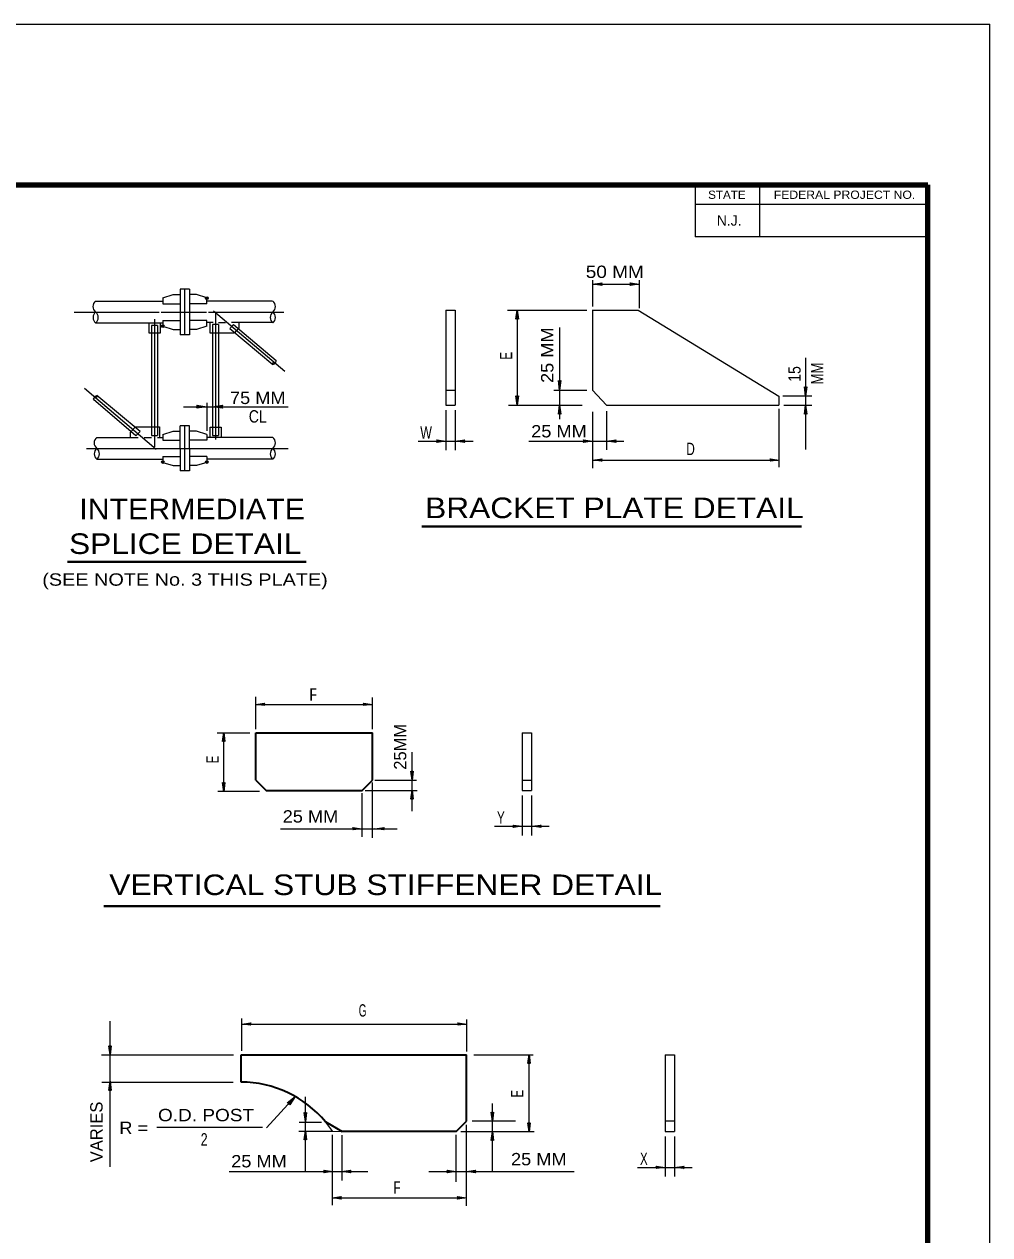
# Model space of a CAD drawing. Extents: x 312601.858 to 312602.699, y 144420.109 to 144420.704.
# Drawn here: x 312602.4645 to 312602.6988, y 144420.4096 to 144420.7035 of the extents above; entities that cross this region are included whole.
import ezdxf
from ezdxf.enums import TextEntityAlignment as Align

# ---------------------------------------------------------------- set-up
doc = ezdxf.new("R2010")
doc.units = 0
doc.header["$LTSCALE"] = 0.0012
doc.header["$PDMODE"] = 32
doc.header["$PDSIZE"] = 0.0006
doc.linetypes.add('DOT_DASHED', pattern=[7.7, 5, -1.2, 0.3, -1.2])
for name, color, linetype, lineweight in [('1', 7, 'Continuous', 13), ('2', 7, 'Continuous', 25), ('39', 7, 'Continuous', 13), ('61', 7, 'Continuous', 25)]:
    doc.layers.add(name, color=color, linetype=linetype, lineweight=lineweight)

msp = doc.modelspace()

# ---------------------------------------------------------------- hatches: boundary and pattern name
at = {"layer": '39'}
for points in [[(312602.5066, 144420.6106), (312602.5064, 144420.611), (312602.5088, 144420.6106), (312602.5064, 144420.6103)], [(312602.5124, 144420.6106), (312602.5126, 144420.6103), (312602.5102, 144420.6106), (312602.5126, 144420.611)], [(312602.5287, 144420.4416), (312602.5283, 144420.4417), (312602.5302, 144420.4432), (312602.5289, 144420.4412)]]:
    msp.add_hatch(color=256, dxfattribs=at).paths.add_polyline_path(points)

# ---------------------------------------------------------------- linework, layer by layer
at = {"layer": '1', "lineweight": 25}
for p, q in [((312602.5023, 144420.6392), (312602.5023, 144420.6281)), ((312602.5046, 144420.6392), (312602.5023, 144420.6392)), ((312602.5034, 144420.6392), (312602.5034, 144420.6281)), ((312602.5046, 144420.6392), (312602.5046, 144420.6281)), ((312602.4818, 144420.6363), (312602.4981, 144420.6363)), ((312602.4981, 144420.6371), (312602.5006, 144420.6379)), ((312602.4981, 144420.6371), (312602.4981, 144420.6356)), ((312602.5006, 144420.6379), (312602.5023, 144420.6379)), ((312602.5063, 144420.6379), (312602.5046, 144420.6379)), ((312602.5088, 144420.6371), (312602.5063, 144420.6379)), ((312602.5088, 144420.6356), (312602.5088, 144420.6371)), ((312602.5247, 144420.6363), (312602.5088, 144420.6363)), ((312602.4981, 144420.6356), (312602.5023, 144420.6356)), ((312602.5088, 144420.6356), (312602.5046, 144420.6356)), ((312602.5668, 144420.6341), (312602.5691, 144420.6341)), ((312602.5668, 144420.6341), (312602.5668, 144420.611)), ((312602.5691, 144420.6341), (312602.5691, 144420.611)), ((312602.6023, 144420.6341), (312602.6135, 144420.6341)), ((312602.6024, 144420.6341), (312602.6024, 144420.6147)), ((312602.6135, 144420.6341), (312602.6476, 144420.6132)), ((312602.4818, 144420.631), (312602.498, 144420.631)), ((312602.4954, 144420.6304), (312602.4954, 144420.6037)), ((312602.4968, 144420.6304), (312602.4954, 144420.6304)), ((312602.4968, 144420.631), (312602.4973, 144420.631)), ((312602.4968, 144420.6304), (312602.4968, 144420.6037)), ((312602.4971, 144420.631), (312602.4973, 144420.631)), ((312602.4973, 144420.631), (312602.4981, 144420.631)), ((312602.4981, 144420.6316), (312602.5023, 144420.6316)), ((312602.4981, 144420.6316), (312602.4981, 144420.6302)), ((312602.4981, 144420.6302), (312602.5006, 144420.6294)), ((312602.5088, 144420.6316), (312602.5046, 144420.6316)), ((312602.5088, 144420.6302), (312602.5063, 144420.6294)), ((312602.5088, 144420.6302), (312602.5088, 144420.6316)), ((312602.5096, 144420.6311), (312602.5088, 144420.6311)), ((312602.5103, 144420.6311), (312602.5096, 144420.6311)), ((312602.5099, 144420.6311), (312602.5096, 144420.6311)), ((312602.5102, 144420.6306), (312602.5102, 144420.6037)), ((312602.5116, 144420.6306), (312602.5102, 144420.6306)), ((312602.5116, 144420.6311), (312602.5133, 144420.6311)), ((312602.5116, 144420.6306), (312602.5116, 144420.6037)), ((312602.5144, 144420.6296), (312602.5153, 144420.6306)), ((312602.5248, 144420.6311), (312602.5148, 144420.6311)), ((312602.5153, 144420.6306), (312602.5256, 144420.6219)), ((312602.5006, 144420.6294), (312602.5023, 144420.6294)), ((312602.5046, 144420.6281), (312602.5023, 144420.6281)), ((312602.5063, 144420.6294), (312602.5046, 144420.6294)), ((312602.5144, 144420.6296), (312602.5248, 144420.6209)), ((312602.4916, 144420.6036), (312602.4813, 144420.6124)), ((312602.4926, 144420.6046), (312602.4821, 144420.6134)), ((312602.5668, 144420.6147), (312602.5691, 144420.6147)), ((312602.6024, 144420.6147), (312602.6058, 144420.611)), ((312602.6476, 144420.6132), (312602.6476, 144420.611)), ((312602.5668, 144420.611), (312602.5691, 144420.611)), ((312602.6058, 144420.611), (312602.6476, 144420.611)), ((312602.4916, 144420.6036), (312602.4926, 144420.6046)), ((312602.4954, 144420.6037), (312602.4968, 144420.6037)), ((312602.4981, 144420.6039), (312602.5006, 144420.6047)), ((312602.4981, 144420.6039), (312602.4981, 144420.6025)), ((312602.5006, 144420.6047), (312602.5023, 144420.6047)), ((312602.5023, 144420.6006), (312602.5023, 144420.606)), ((312602.5034, 144420.606), (312602.5034, 144420.5951)), ((312602.5046, 144420.6006), (312602.5046, 144420.606)), ((312602.5063, 144420.6047), (312602.5046, 144420.6047)), ((312602.5088, 144420.6039), (312602.5063, 144420.6047)), ((312602.5088, 144420.6039), (312602.5088, 144420.6025)), ((312602.5102, 144420.6037), (312602.5116, 144420.6037)), ((312602.4821, 144420.6032), (312602.4921, 144420.6032)), ((312602.4936, 144420.6032), (312602.4954, 144420.6032)), ((312602.4968, 144420.6032), (312602.4973, 144420.6032)), ((312602.4971, 144420.6032), (312602.4973, 144420.6032)), ((312602.4973, 144420.6032), (312602.4981, 144420.6032)), ((312602.4981, 144420.6025), (312602.5023, 144420.6025)), ((312602.5088, 144420.6025), (312602.5046, 144420.6025)), ((312602.5096, 144420.6032), (312602.5088, 144420.6032)), ((312602.5248, 144420.6032), (312602.509, 144420.6032)), ((312602.5102, 144420.6032), (312602.5096, 144420.6032)), ((312602.5099, 144420.6032), (312602.5096, 144420.6032)), ((312602.4821, 144420.5979), (312602.4981, 144420.5979)), ((312602.4981, 144420.5986), (312602.5023, 144420.5986)), ((312602.4981, 144420.5986), (312602.4981, 144420.5971)), ((312602.5023, 144420.6006), (312602.5023, 144420.5951)), ((312602.5046, 144420.6006), (312602.5046, 144420.5951)), ((312602.5088, 144420.5986), (312602.5046, 144420.5986)), ((312602.5088, 144420.5986), (312602.5088, 144420.5971)), ((312602.5248, 144420.5979), (312602.5088, 144420.5979)), ((312602.4981, 144420.5971), (312602.5006, 144420.5964)), ((312602.5006, 144420.5964), (312602.5023, 144420.5964)), ((312602.5063, 144420.5964), (312602.5046, 144420.5964)), ((312602.5088, 144420.5971), (312602.5063, 144420.5964)), ((312602.5853, 144420.5315), (312602.5853, 144420.5175)), ((312602.5853, 144420.5315), (312602.5876, 144420.5315)), ((312602.5876, 144420.5315), (312602.5876, 144420.5175)), ((312602.5853, 144420.52), (312602.5876, 144420.52)), ((312602.5853, 144420.5175), (312602.5876, 144420.5175)), ((312602.62, 144420.4533), (312602.62, 144420.4347)), ((312602.62, 144420.4533), (312602.6223, 144420.4533)), ((312602.6223, 144420.4533), (312602.6223, 144420.4347)), ((312602.62, 144420.4373), (312602.6223, 144420.4373)), ((312602.62, 144420.4347), (312602.6223, 144420.4347))]:
    msp.add_line(p, q, dxfattribs=at)
at = {"layer": '1'}
for p, q in [((312602.6024, 144420.6414), (312602.6024, 144420.635)), ((312602.6024, 144420.6404), (312602.6137, 144420.6404)), ((312602.6137, 144420.6414), (312602.6137, 144420.6346)), ((312602.5818, 144420.6341), (312602.601, 144420.6341)), ((312602.5841, 144420.6341), (312602.5841, 144420.611)), ((312602.6541, 144420.6225), (312602.6541, 144420.6003)), ((312602.593, 144420.6147), (312602.601, 144420.6147)), ((312602.6556, 144420.6132), (312602.6486, 144420.6132)), ((312602.5031, 144420.6106), (312602.5088, 144420.6106)), ((312602.5088, 144420.6116), (312602.5088, 144420.6048)), ((312602.5088, 144420.6106), (312602.5104, 144420.6106)), ((312602.5102, 144420.6106), (312602.5285, 144420.6106)), ((312602.5668, 144420.6098), (312602.5668, 144420.6001)), ((312602.5691, 144420.6098), (312602.5691, 144420.6001)), ((312602.582, 144420.611), (312602.5999, 144420.611)), ((312602.6058, 144420.6096), (312602.6058, 144420.6002)), ((312602.6476, 144420.6101), (312602.6476, 144420.596)), ((312602.6488, 144420.611), (312602.6556, 144420.611)), ((312602.6024, 144420.6094), (312602.6024, 144420.5957)), ((312602.5046, 144420.606), (312602.5023, 144420.606)), ((312602.5601, 144420.6023), (312602.5668, 144420.6023)), ((312602.6024, 144420.5977), (312602.6474, 144420.5977)), ((312602.5046, 144420.5951), (312602.5023, 144420.5951)), ((312602.5207, 144420.5324), (312602.5207, 144420.5402)), ((312602.549, 144420.5324), (312602.549, 144420.5401)), ((312602.5207, 144420.5384), (312602.549, 144420.5384)), ((312602.5113, 144420.5315), (312602.5192, 144420.5315)), ((312602.5129, 144420.5173), (312602.5129, 144420.5316)), ((312602.5586, 144420.5125), (312602.5586, 144420.5268)), ((312602.549, 144420.506), (312602.549, 144420.5194)), ((312602.5496, 144420.52), (312602.5597, 144420.52)), ((312602.5115, 144420.5173), (312602.5216, 144420.5173)), ((312602.5465, 144420.5062), (312602.5465, 144420.5168)), ((312602.5472, 144420.5175), (312602.5598, 144420.5175)), ((312602.5853, 144420.5163), (312602.5853, 144420.5066)), ((312602.5876, 144420.5163), (312602.5876, 144420.5066)), ((312602.5267, 144420.5082), (312602.555, 144420.5082)), ((312602.5786, 144420.5088), (312602.5853, 144420.5088)), ((312602.4853, 144420.4261), (312602.4853, 144420.4615)), ((312602.5173, 144420.4543), (312602.5173, 144420.4621)), ((312602.5173, 144420.4608), (312602.5719, 144420.4608)), ((312602.5719, 144420.4541), (312602.5719, 144420.4619)), ((312602.4832, 144420.4533), (312602.5153, 144420.4533)), ((312602.5736, 144420.4533), (312602.588, 144420.4533)), ((312602.587, 144420.4347), (312602.587, 144420.4533)), ((312602.4833, 144420.4467), (312602.5152, 144420.4467)), ((312602.5302, 144420.4432), (312602.5233, 144420.4356)), ((312602.5327, 144420.425), (312602.5327, 144420.4431)), ((312602.5781, 144420.425), (312602.5781, 144420.4415)), ((312602.5312, 144420.437), (312602.5366, 144420.437)), ((312602.5376, 144420.437), (312602.5393, 144420.4347)), ((312602.5718, 144420.4167), (312602.5718, 144420.4363)), ((312602.5732, 144420.4373), (312602.5837, 144420.4373)), ((312602.5223, 144420.4357), (312602.4967, 144420.4357)), ((312602.5393, 144420.4168), (312602.5393, 144420.4339)), ((312602.5416, 144420.4228), (312602.5416, 144420.4338)), ((312602.5693, 144420.4225), (312602.5693, 144420.4339)), ((312602.5704, 144420.4347), (312602.5882, 144420.4347)), ((312602.62, 144420.4335), (312602.62, 144420.4238)), ((312602.6223, 144420.4335), (312602.6223, 144420.4238)), ((312602.5142, 144420.425), (312602.5479, 144420.425)), ((312602.5627, 144420.425), (312602.5652, 144420.425)), ((312602.5637, 144420.425), (312602.5979, 144420.425)), ((312602.6133, 144420.426), (312602.62, 144420.426)), ((312602.5394, 144420.4186), (312602.5714, 144420.4186))]:
    msp.add_line(p, q, dxfattribs=at)
at = {"layer": '1', "linetype": 'DOT_DASHED'}
for p, q in [((312602.4766, 144420.6336), (312602.4972, 144420.6336)), ((312602.4977, 144420.6336), (312602.5087, 144420.6336)), ((312602.5092, 144420.6336), (312602.5275, 144420.6336)), ((312602.5104, 144420.6339), (312602.5277, 144420.6193)), ((312602.5109, 144420.6333), (312602.5109, 144420.6027)), ((312602.4961, 144420.6319), (312602.4961, 144420.6009)), ((312602.4965, 144420.6003), (312602.4791, 144420.6151)), ((312602.4796, 144420.6005), (312602.5285, 144420.6005))]:
    msp.add_line(p, q, dxfattribs=at)
at = {"layer": '1', "lineweight": 40}
for p, q in [((312602.561, 144420.5816), (312602.6531, 144420.5816)), ((312602.475, 144420.573), (312602.5329, 144420.573)), ((312602.4838, 144420.4894), (312602.6188, 144420.4894))]:
    msp.add_line(p, q, dxfattribs=at)
at = {"layer": '1', "lineweight": 35}
for p, q in [((312602.5207, 144420.52), (312602.5207, 144420.5315)), ((312602.5207, 144420.5315), (312602.549, 144420.5315)), ((312602.549, 144420.52), (312602.549, 144420.5315)), ((312602.5207, 144420.52), (312602.5232, 144420.5175)), ((312602.5465, 144420.5175), (312602.549, 144420.52)), ((312602.5232, 144420.5175), (312602.5465, 144420.5175)), ((312602.5171, 144420.4533), (312602.5718, 144420.4533)), ((312602.5171, 144420.4467), (312602.5171, 144420.4533)), ((312602.5718, 144420.4372), (312602.5718, 144420.4533)), ((312602.5375, 144420.4371), (312602.5416, 144420.4347)), ((312602.5693, 144420.4347), (312602.5718, 144420.4372)), ((312602.5693, 144420.4347), (312602.5416, 144420.4347))]:
    msp.add_line(p, q, dxfattribs=at)
at = {"layer": '1'}
for points in [[(312602.6047, 144420.6401), (312602.6024, 144420.6404), (312602.6047, 144420.6407), (312602.6044, 144420.6404)], [(312602.6115, 144420.6407), (312602.6137, 144420.6404), (312602.6115, 144420.6401), (312602.6117, 144420.6404)], [(312602.5838, 144420.6319), (312602.5841, 144420.6341), (312602.5844, 144420.6319), (312602.5841, 144420.6321)], [(312602.5947, 144420.617), (312602.5944, 144420.6147), (312602.5941, 144420.617), (312602.5944, 144420.6167)], [(312602.6544, 144420.6155), (312602.6541, 144420.6132), (312602.6538, 144420.6155), (312602.6541, 144420.6152)], [(312602.5844, 144420.6133), (312602.5841, 144420.611), (312602.5838, 144420.6133), (312602.5841, 144420.613)], [(312602.5941, 144420.6088), (312602.5944, 144420.611), (312602.5947, 144420.6088), (312602.5944, 144420.609)], [(312602.6538, 144420.6088), (312602.6541, 144420.611), (312602.6544, 144420.6088), (312602.6541, 144420.609)], [(312602.5646, 144420.6026), (312602.5668, 144420.6023), (312602.5646, 144420.602), (312602.5648, 144420.6023)], [(312602.5714, 144420.602), (312602.5691, 144420.6023), (312602.5714, 144420.6026), (312602.5711, 144420.6023)], [(312602.6002, 144420.6026), (312602.6024, 144420.6023), (312602.6002, 144420.602), (312602.6004, 144420.6023)], [(312602.6081, 144420.602), (312602.6058, 144420.6023), (312602.6081, 144420.6026), (312602.6078, 144420.6023)], [(312602.6047, 144420.5974), (312602.6024, 144420.5977), (312602.6047, 144420.598), (312602.6044, 144420.5977)], [(312602.6455, 144420.598), (312602.6477, 144420.5977), (312602.6455, 144420.5974), (312602.6457, 144420.5977)], [(312602.5228, 144420.5381), (312602.5206, 144420.5384), (312602.5228, 144420.5387), (312602.5226, 144420.5384)], [(312602.5468, 144420.5387), (312602.549, 144420.5384), (312602.5468, 144420.5381), (312602.547, 144420.5384)], [(312602.5126, 144420.5294), (312602.5129, 144420.5316), (312602.5132, 144420.5294), (312602.5129, 144420.5296)], [(312602.5589, 144420.5222), (312602.5586, 144420.52), (312602.5583, 144420.5222), (312602.5586, 144420.522)], [(312602.5132, 144420.5194), (312602.5129, 144420.5172), (312602.5126, 144420.5194), (312602.5129, 144420.5192)], [(312602.5583, 144420.5154), (312602.5586, 144420.5176), (312602.5589, 144420.5154), (312602.5586, 144420.5156)], [(312602.5442, 144420.5085), (312602.5464, 144420.5082), (312602.5442, 144420.5079), (312602.5444, 144420.5082)], [(312602.5518, 144420.5079), (312602.5496, 144420.5082), (312602.5518, 144420.5085), (312602.5516, 144420.5082)], [(312602.5831, 144420.5091), (312602.5853, 144420.5088), (312602.5831, 144420.5085), (312602.5833, 144420.5088)], [(312602.5899, 144420.5085), (312602.5876, 144420.5088), (312602.5899, 144420.5091), (312602.5896, 144420.5088)], [(312602.5195, 144420.4605), (312602.5173, 144420.4608), (312602.5195, 144420.4611), (312602.5193, 144420.4608)], [(312602.5697, 144420.4611), (312602.5719, 144420.4608), (312602.5697, 144420.4605), (312602.5699, 144420.4608)], [(312602.4856, 144420.4555), (312602.4853, 144420.4533), (312602.485, 144420.4555), (312602.4853, 144420.4553)], [(312602.5867, 144420.4512), (312602.587, 144420.4534), (312602.5873, 144420.4512), (312602.587, 144420.4514)], [(312602.485, 144420.4447), (312602.4853, 144420.4469), (312602.4856, 144420.4447), (312602.4853, 144420.4449)], [(312602.533, 144420.4393), (312602.5327, 144420.4371), (312602.5324, 144420.4393), (312602.5327, 144420.4391)], [(312602.5784, 144420.4394), (312602.5781, 144420.4372), (312602.5778, 144420.4394), (312602.5781, 144420.4392)], [(312602.5873, 144420.4368), (312602.587, 144420.4346), (312602.5867, 144420.4368), (312602.587, 144420.4366)], [(312602.5324, 144420.4327), (312602.5327, 144420.4349), (312602.533, 144420.4327), (312602.5327, 144420.4329)], [(312602.5778, 144420.4325), (312602.5781, 144420.4347), (312602.5784, 144420.4325), (312602.5781, 144420.4327)], [(312602.5372, 144420.4253), (312602.5394, 144420.425), (312602.5372, 144420.4247), (312602.5374, 144420.425)], [(312602.5437, 144420.4247), (312602.5415, 144420.425), (312602.5437, 144420.4253), (312602.5435, 144420.425)], [(312602.5671, 144420.4253), (312602.5693, 144420.425), (312602.5671, 144420.4247), (312602.5673, 144420.425)], [(312602.574, 144420.4247), (312602.5718, 144420.425), (312602.574, 144420.4253), (312602.5738, 144420.425)], [(312602.6178, 144420.4263), (312602.62, 144420.426), (312602.6178, 144420.4257), (312602.618, 144420.426)], [(312602.6246, 144420.4257), (312602.6223, 144420.426), (312602.6246, 144420.4263), (312602.6243, 144420.426)], [(312602.5414, 144420.4183), (312602.5392, 144420.4186), (312602.5414, 144420.4189), (312602.5412, 144420.4186)], [(312602.5696, 144420.4189), (312602.5718, 144420.4186), (312602.5696, 144420.4183), (312602.5698, 144420.4186)]]:
    msp.add_lwpolyline(points, close=True, dxfattribs=at)
at = {"layer": '1', "lineweight": 25}
for points in [[(312602.4975, 144420.631), (312602.4975, 144420.6285), (312602.4948, 144420.6285), (312602.4948, 144420.631)], [(312602.5154, 144420.6285), (312602.5096, 144420.6285), (312602.5096, 144420.6311)], [(312602.5154, 144420.6285), (312602.5096, 144420.6285), (312602.5096, 144420.6311)], [(312602.5166, 144420.6311), (312602.5166, 144420.6298), (312602.5154, 144420.6285)], [(312602.5166, 144420.6311), (312602.5166, 144420.6298), (312602.5154, 144420.6285)], [(312602.4903, 144420.6032), (312602.4903, 144420.6045), (312602.4915, 144420.6058)], [(312602.4915, 144420.6058), (312602.4973, 144420.6058), (312602.4973, 144420.6032)], [(312602.5096, 144420.6032), (312602.5096, 144420.6057), (312602.5123, 144420.6057), (312602.5123, 144420.6032)]]:
    msp.add_lwpolyline(points, dxfattribs=at)
at = {"layer": '1'}
for points in [[(312602.5944, 144420.6299), (312602.5944, 144420.6147), (312602.5944, 144420.611), (312602.5944, 144420.6076)], [(312602.5668, 144420.6023), (312602.5691, 144420.6023), (312602.5734, 144420.6023)], [(312602.5869, 144420.6023), (312602.6024, 144420.6023), (312602.6058, 144420.6023), (312602.61, 144420.6023)], [(312602.5853, 144420.5088), (312602.5876, 144420.5088), (312602.5919, 144420.5088)], [(312602.5311, 144420.4348), (312602.539, 144420.4348), (312602.5416, 144420.4347)], [(312602.62, 144420.426), (312602.6223, 144420.426), (312602.6266, 144420.426)]]:
    msp.add_lwpolyline(points, dxfattribs=at)
at = {"layer": '1', "lineweight": 35}
msp.add_arc((312602.5171, 144420.4202), 0.0265, 39.48086, 89.99981, dxfattribs=at)
at = {"layer": '1'}
for centre, major_axis in [((312602.524962, 144420.621149), (-0.00023457, -0.00024613)), ((312602.481918, 144420.613071), (0.00023457, 0.00024613))]:
    msp.add_ellipse(centre, major_axis=major_axis, ratio=0.57735, dxfattribs=at)
for centre, major_axis in [((312602.525387, 144420.621659), (-0.00021847, -0.00022924)), ((312602.481493, 144420.612561), (0.00021847, 0.00022924))]:
    msp.add_ellipse(centre, major_axis=major_axis, ratio=0.619877, start_param=0, end_param=3.141592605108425, dxfattribs=at)
for p in [(312602.5088, 144420.637), (312602.4981, 144420.6302), (312602.4981, 144420.5972), (312602.5088, 144420.5972)]:
    msp.add_point(p, dxfattribs=at)
at = {"layer": '2'}
for centre, start, end in [((312602.482833, 144420.6323), 128.4802, 231.5198), ((312602.480767, 144420.6323), 308.4802, 51.5198), ((312602.525833, 144420.6323), 128.4802, 231.5198), ((312602.523767, 144420.6323), 308.4802, 51.5198), ((312602.483133, 144420.5992), 128.4802, 231.5198), ((312602.481067, 144420.5992), 308.4802, 51.5198), ((312602.525833, 144420.5992), 128.4802, 231.5198), ((312602.523767, 144420.5992), 308.4802, 51.5198)]:
    msp.add_arc(centre, 0.0016607, start, end, dxfattribs=at)
for centre, major_axis, start_param, end_param in [((312602.482833, 144420.635), (-0.00134033, -0.00106539), 4.71238898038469, 6.5404266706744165), ((312602.523767, 144420.635), (-0.00134033, 0.00106539), 2.884351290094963, 4.71238898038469), ((312602.483133, 144420.6019), (-0.00134033, -0.00106539), 4.71238898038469, 6.5404266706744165), ((312602.523767, 144420.6019), (-0.00134033, 0.00106539), 2.884351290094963, 4.71238898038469)]:
    msp.add_ellipse(centre, major_axis=major_axis, ratio=0.96991, start_param=start_param, end_param=end_param, dxfattribs=at)
at = {"layer": '39', "lineweight": 25}
for p, q in [((312601.8578, 144420.7035), (312602.6988, 144420.7035)), ((312602.6988, 144420.1095), (312602.6988, 144420.7035)), ((312602.5735, 144420.6645), (312602.6838, 144420.6645)), ((312602.6838, 144420.6514), (312602.6838, 144420.6645))]:
    msp.add_line(p, q, dxfattribs=at)
at = {"layer": '39', "lineweight": 158}
for p in [(312601.9088, 144420.6645), (312602.6838, 144420.1247)]:
    msp.add_line(p, (312602.6838, 144420.6645), dxfattribs=at)
at = {"layer": '39'}
for points in [[(312602.5066, 144420.6106), (312602.5064, 144420.611), (312602.5088, 144420.6106), (312602.5064, 144420.6103)], [(312602.5124, 144420.6106), (312602.5126, 144420.6103), (312602.5102, 144420.6106), (312602.5126, 144420.611)], [(312602.5287, 144420.4416), (312602.5283, 144420.4417), (312602.5302, 144420.4432), (312602.5289, 144420.4412)]]:
    msp.add_lwpolyline(points, close=True, dxfattribs=at)
at = {"layer": '61'}
for p, q in [((312602.6273, 144420.6645), (312602.6273, 144420.6519)), ((312602.6429, 144420.6645), (312602.6429, 144420.6519)), ((312602.6838, 144420.6597), (312602.6273, 144420.6597)), ((312602.6838, 144420.6519), (312602.6273, 144420.6519))]:
    msp.add_line(p, q, dxfattribs=at)

# ---------------------------------------------------------------- texts
at = {"layer": '2'}
for s, height, width, p in [('50 MM', 0.003, 1.15, (312602.6078, 144420.6419)), ('75 MM', 0.003, 1.1, (312602.52115, 144420.6113)), ('CL', 0.003, 0.85, (312602.52115, 144420.6068)), ('W', 0.003, 0.75, (312602.562, 144420.6029)), ('25 MM', 0.003, 1.1, (312602.59425, 144420.6032)), ('D', 0.003, 0.7, (312602.6262, 144420.5989)), ('INTERMEDIATE ', 0.005, 1.1, (312602.50625, 144420.5833)), ('BRACKET PLATE DETAIL', 0.005, 1.15, (312602.6077, 144420.5836)), ('SPLICE DETAIL', 0.005, 1.15, (312602.50355, 144420.5749)), ('(SEE NOTE No. 3 THIS PLATE)', 0.003, 1.2, (312602.5035, 144420.5672)), ('F', 0.003, 0.7, (312602.53455, 144420.5393)), ('F', 0.003, 0.7, (312602.53465, 144420.5393)), ('25 MM', 0.003, 1.1, (312602.53395, 144420.5097)), ('Y', 0.003, 0.7, (312602.58015, 144420.5094)), ('VERTICAL STUB STIFFENER DETAIL', 0.005, 1.15, (312602.5522, 144420.4921)), ('G', 0.003, 0.6, (312602.5466, 144420.4626)), ('O.D. POST', 0.003, 1.15, (312602.5086, 144420.4372)), ('R =', 0.003, 1.1, (312602.49105, 144420.4341)), ('2', 0.003, 0.75, (312602.50815, 144420.4313)), ('25 MM', 0.003, 1.1, (312602.52145, 144420.426)), ('25 MM', 0.003, 1.1, (312602.58935, 144420.4265)), ('X', 0.003, 0.7, (312602.61485, 144420.4266)), ('F', 0.003, 0.7, (312602.55495, 144420.4196))]:
    msp.add_text(s, height=height, dxfattribs=dict(at, width=width)).set_placement(p, align=Align.CENTER)
for s, height, width, p in [('25 MM', 0.003, 1.1, (312602.5929, 144420.62315)), ('E', 0.002999, 0.7, (312602.5829, 144420.623)), ('15', 0.003, 0.85, (312602.6529, 144420.6186)), ('MM', 0.003, 0.8, (312602.6584, 144420.6187)), ('E', 0.003, 0.7, (312602.5117, 144420.525)), ('E', 0.003, 0.7, (312602.5856, 144420.4439))]:
    msp.add_text(s, height=height, rotation=90, dxfattribs=dict(at, width=width)).set_placement(p, align=Align.CENTER)
for s, p in [('25MM', (312602.5572, 144420.5281)), ('VARIES', (312602.4835, 144420.4346))]:
    msp.add_text(s, height=0.003, rotation=90, dxfattribs=at).set_placement(p, align=Align.CENTER)
at = {"layer": '61'}
for s, width, p in [('STATE', 1.05, (312602.635, 144420.6611)), ('FEDERAL PROJECT NO.', 1.1, (312602.66355, 144420.6611))]:
    msp.add_text(s, height=0.00201, dxfattribs=dict(at, width=width)).set_placement(p, align=Align.CENTER)
msp.add_text('N.J.', height=0.002512, dxfattribs=at).set_placement((312602.63555, 144420.6546), align=Align.CENTER)

doc.saveas('drawing.dxf')
